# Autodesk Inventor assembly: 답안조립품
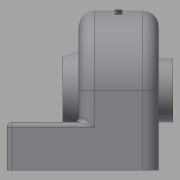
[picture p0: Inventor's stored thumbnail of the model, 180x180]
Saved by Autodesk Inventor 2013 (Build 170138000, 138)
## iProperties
Created: 2015-02
Part Number: 답안조립품
Document SubType Name: Assembly
Designer: Administrator
Author: Administrator
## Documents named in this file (2)
- C:\Users\Administrator\Desktop\450216V1003\답안조립품.iam
- C:\Users\Administrator\Desktop\450216V1003\본체.ipt
